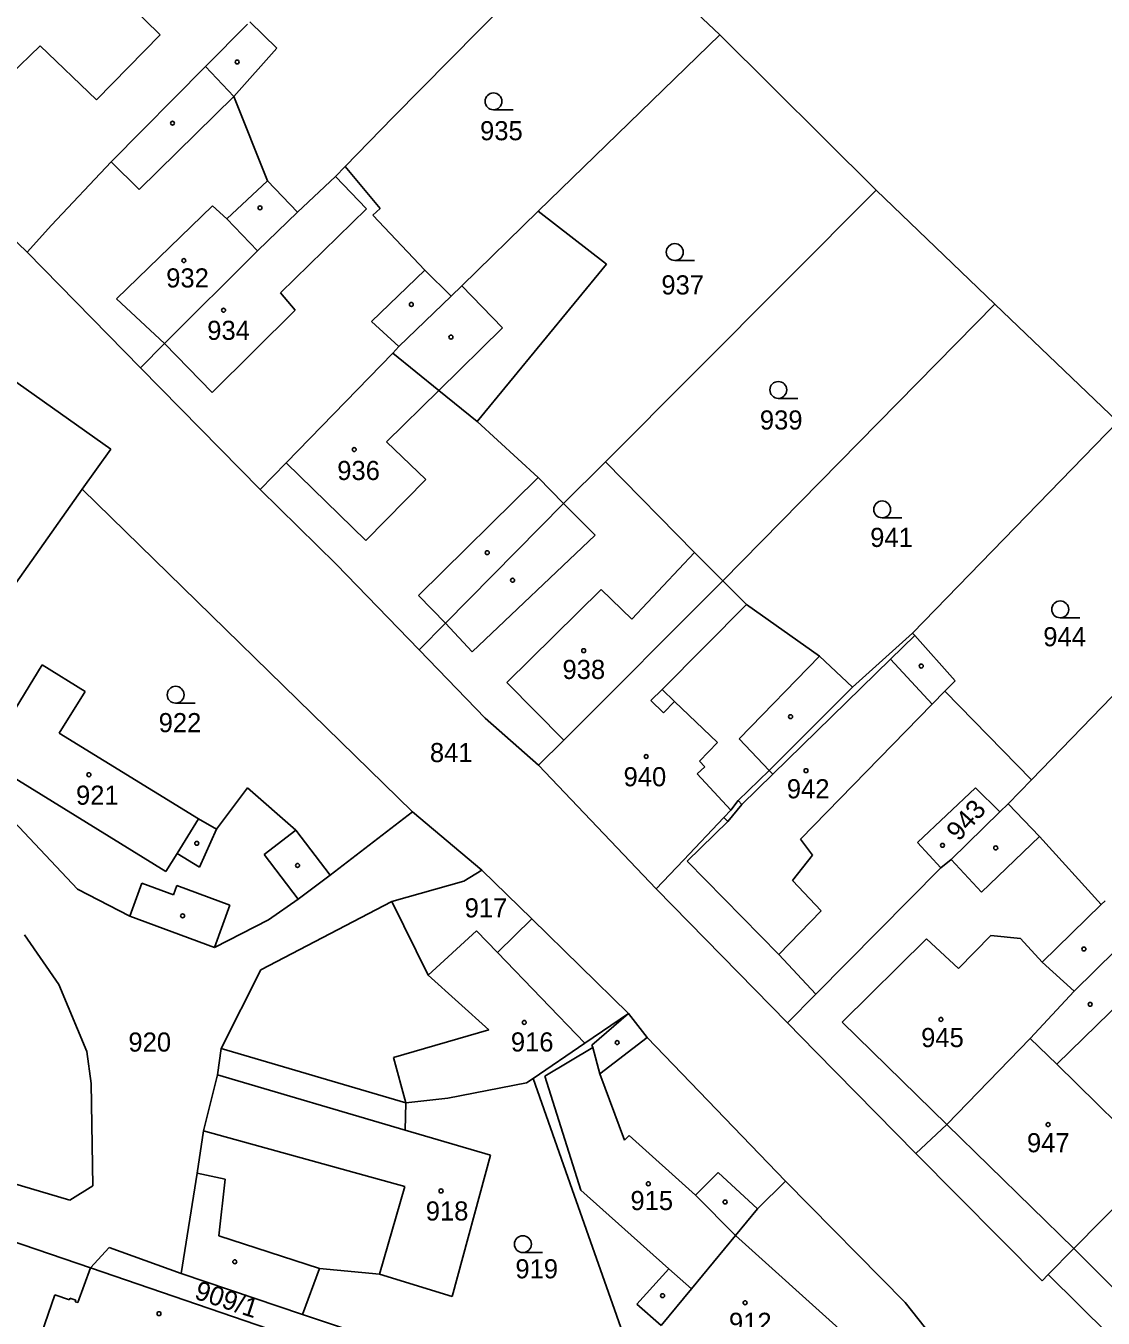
# Model space of a CAD drawing. Extents: x -779596 to -776743, y -1030330 to -1024513.
# Drawn here: x -777631 to -777535.2, y -1025565.5 to -1025450.6 of the extents above; entities that cross this region are included whole.
import ezdxf

# ---------------------------------------------------------------- set-up
doc = ezdxf.new("R2010")
doc.units = 0
for name, color, linetype in [('hranice parcel', 7, 'Continuous'), ('hranice vnitřní', 7, 'Continuous'), ('kultura', 7, 'Continuous'), ('č_ parcel šipka', 7, 'Continuous'), ('č_pacel stav_', 7, 'Continuous'), ('č_parcel poz_', 7, 'Continuous')]:
    doc.layers.add(name, color=color, linetype=linetype)

msp = doc.modelspace()

# ---------------------------------------------------------------- linework, layer by layer
at = {"layer": 'hranice parcel'}
for points in [[(-777629.79, -1025440.88), (-777619.04, -1025451.43)], [(-777598.32, -1025458.73), (-777580.56, -1025440.75)], [(-777580.56, -1025440.75), (-777569.28, -1025451.43)], [(-777611.07, -1025450.25), (-777608.66, -1025452.61)], [(-777615, -1025454.22), (-777611.28, -1025450.46)], [(-777632.41, -1025455), (-777629.71, -1025452.38)], [(-777629.71, -1025452.38), (-777624.69, -1025457.19)], [(-777624.69, -1025457.19), (-777619.04, -1025451.43)], [(-777585.41, -1025467.1), (-777569.28, -1025451.43)], [(-777569.28, -1025451.43), (-777555.38, -1025465.23)], [(-777612.5, -1025456.89), (-777608.66, -1025452.61)], [(-777623.4, -1025462.71), (-777615, -1025454.22)], [(-777612.5, -1025456.89), (-777609.5, -1025464.41)], [(-777602.6, -1025463.12), (-777598.32, -1025458.73)], [(-777628.69, -1025468.34), (-777623.4, -1025462.71)], [(-777606.82, -1025467.18), (-777603.46, -1025464)], [(-777603.46, -1025464), (-777602.6, -1025463.12)], [(-777602.6, -1025463.12), (-777599.48, -1025466.85)], [(-777609.5, -1025464.41), (-777606.82, -1025467.18)], [(-777579.44, -1025489.37), (-777555.38, -1025465.23)], [(-777555.38, -1025465.23), (-777544.81, -1025475.35)], [(-777610.37, -1025470.63), (-777606.82, -1025467.18)], [(-777600.12, -1025467.46), (-777599.48, -1025466.85)], [(-777600.12, -1025467.46), (-777595.49, -1025472.33)], [(-777592.22, -1025473.74), (-777585.41, -1025467.1)], [(-777585.41, -1025467.1), (-777579.34, -1025471.82)], [(-777634.25, -1025467.51), (-777630.86, -1025470.74)], [(-777630.86, -1025470.74), (-777628.69, -1025468.34)], [(-777630.86, -1025470.74), (-777620.79, -1025481.01)], [(-777618.65, -1025478.87), (-777610.37, -1025470.63)], [(-777590.85, -1025485.79), (-777579.34, -1025471.82)], [(-777595.49, -1025472.33), (-777593.16, -1025474.64)], [(-777593.16, -1025474.64), (-777592.22, -1025473.74)], [(-777597.8, -1025479.14), (-777593.16, -1025474.64)], [(-777568.99, -1025499.96), (-777544.81, -1025475.35)], [(-777544.81, -1025475.35), (-777533.87, -1025485.82)], [(-777620.79, -1025481.01), (-777618.65, -1025478.87)], [(-777635.46, -1025479.74), (-777623.41, -1025488.25)], [(-777607.83, -1025489.46), (-777598.35, -1025479.71)], [(-777598.35, -1025479.71), (-777597.8, -1025479.14)], [(-777620.79, -1025481.01), (-777610.14, -1025491.85)], [(-777590.85, -1025485.79), (-777585.43, -1025490.78)], [(-777552.15, -1025504.61), (-777533.87, -1025485.82)], [(-777625.98, -1025491.82), (-777623.41, -1025488.25)], [(-777610.14, -1025491.85), (-777607.83, -1025489.46)], [(-777583.16, -1025493.1), (-777579.44, -1025489.37)], [(-777579.44, -1025489.37), (-777571.52, -1025497.43)], [(-777585.43, -1025490.78), (-777583.16, -1025493.1)], [(-777639.77, -1025511.34), (-777625.98, -1025491.82)], [(-777625.98, -1025491.82), (-777596.6, -1025520.49)], [(-777610.14, -1025491.85), (-777603.39, -1025498.47)], [(-777593.67, -1025503.72), (-777583.16, -1025493.1)], [(-777541.56, -1025517.67), (-777521.9, -1025497.36)], [(-777603.39, -1025498.47), (-777596.02, -1025506.09)], [(-777571.52, -1025497.43), (-777568.99, -1025499.96)], [(-777583.13, -1025514.12), (-777568.99, -1025499.96)], [(-777568.99, -1025499.96), (-777566.89, -1025502.08)], [(-777566.89, -1025502.08), (-777560.42, -1025506.65)], [(-777596.02, -1025506.09), (-777593.67, -1025503.72)], [(-777557.48, -1025509.41), (-777552.15, -1025504.61)], [(-777552.15, -1025504.61), (-777551.94, -1025504.83)], [(-777551.94, -1025504.83), (-777548.35, -1025508.85)], [(-777596.02, -1025506.09), (-777590.13, -1025512.17)], [(-777634.7, -1025515.86), (-777629.53, -1025507.44)], [(-777629.53, -1025507.44), (-777625.71, -1025509.79)], [(-777560.42, -1025506.65), (-777557.48, -1025509.41)], [(-777549.25, -1025509.78), (-777548.35, -1025508.85)], [(-777628.01, -1025513.52), (-777625.71, -1025509.79)], [(-777564.88, -1025516.82), (-777557.48, -1025509.41)], [(-777549.25, -1025509.78), (-777541.56, -1025517.67)], [(-777590.13, -1025512.17), (-777585.4, -1025516.35)], [(-777628.01, -1025513.52), (-777615.64, -1025521.12)], [(-777585.4, -1025516.35), (-777583.13, -1025514.12)], [(-777585.4, -1025516.35), (-777574.92, -1025527.34)], [(-777567.65, -1025519.48), (-777564.88, -1025516.82)], [(-777635.86, -1025517.33), (-777626.39, -1025527.37)], [(-777543.62, -1025519.79), (-777541.56, -1025517.67)], [(-777614.03, -1025522.05), (-777611.28, -1025518.38)], [(-777611.28, -1025518.38), (-777606.97, -1025522.13)], [(-777551.68, -1025523.24), (-777546.55, -1025518.36)], [(-777546.55, -1025518.36), (-777544.36, -1025520.49)], [(-777568.92, -1025521.01), (-777568.3, -1025520.35)], [(-777568.3, -1025520.35), (-777567.65, -1025519.48)], [(-777544.36, -1025520.49), (-777543.62, -1025519.79)], [(-777543.62, -1025519.79), (-777540.86, -1025522.69)], [(-777615.64, -1025521.12), (-777614.03, -1025522.05)], [(-777603.93, -1025526.12), (-777596.6, -1025520.49)], [(-777596.6, -1025520.49), (-777590.42, -1025525.69)], [(-777572.5, -1025524.79), (-777568.92, -1025521.01)], [(-777548.69, -1025524.74), (-777544.36, -1025520.49)], [(-777606.97, -1025522.13), (-777603.93, -1025526.12)], [(-777551.68, -1025523.24), (-777549.63, -1025525.48)], [(-777540.86, -1025522.69), (-777535.36, -1025528.75)], [(-777574.92, -1025527.34), (-777572.5, -1025524.79)], [(-777549.63, -1025525.48), (-777548.69, -1025524.74)], [(-777592.04, -1025526.66), (-777590.42, -1025525.69)], [(-777590.42, -1025525.69), (-777585.99, -1025530.01)], [(-777560.74, -1025536.7), (-777549.63, -1025525.48)], [(-777606.76, -1025528.28), (-777603.93, -1025526.12)], [(-777598.43, -1025528.47), (-777592.04, -1025526.66)], [(-777626.39, -1025527.37), (-777621.74, -1025529.79)], [(-777609.4, -1025530.1), (-777606.76, -1025528.28)], [(-777574.92, -1025527.34), (-777563.26, -1025539.25)], [(-777610.07, -1025534.56), (-777598.43, -1025528.47)], [(-777598.43, -1025528.47), (-777595.21, -1025535.03)], [(-777535.36, -1025528.75), (-777535.01, -1025528.41)], [(-777621.74, -1025529.79), (-777614.21, -1025532.56)], [(-777614.21, -1025532.56), (-777609.4, -1025530.1)], [(-777589.04, -1025533.02), (-777585.99, -1025530.01)], [(-777585.99, -1025530.01), (-777577.38, -1025538.42)], [(-777631.1, -1025531.44), (-777628.04, -1025535.86)], [(-777595.21, -1025535.03), (-777590.91, -1025531.07)], [(-777590.91, -1025531.07), (-777589.04, -1025533.02)], [(-777537.75, -1025536.44), (-777532.18, -1025530.97)], [(-777613.6, -1025541.54), (-777610.07, -1025534.56)], [(-777628.04, -1025535.86), (-777625.56, -1025541.81)], [(-777563.26, -1025539.25), (-777560.74, -1025536.7)], [(-777541.69, -1025540.65), (-777537.75, -1025536.44)], [(-777581.28, -1025541.08), (-777577.38, -1025538.42)], [(-777577.38, -1025538.42), (-777575.73, -1025540.57)], [(-777563.26, -1025539.25), (-777560.72, -1025541.84)], [(-777575.73, -1025540.57), (-777563.42, -1025553.35)], [(-777549.1, -1025548.3), (-777541.69, -1025540.65)], [(-777625.56, -1025541.81), (-777625.17, -1025544.67)], [(-777613.94, -1025543.9), (-777613.6, -1025541.54)], [(-777613.6, -1025541.54), (-777597.2, -1025546.38)], [(-777585.87, -1025544.2), (-777581.28, -1025541.08)], [(-777560.72, -1025541.84), (-777551.84, -1025550.89)], [(-777615.17, -1025548.86), (-777613.94, -1025543.9)], [(-777586.45, -1025544.59), (-777585.87, -1025544.2)], [(-777585.87, -1025544.2), (-777582.41, -1025554.07)], [(-777625.17, -1025544.67), (-777625.01, -1025553.76)], [(-777593.45, -1025545.95), (-777586.45, -1025544.59)], [(-777597.26, -1025548.8), (-777597.2, -1025546.38)], [(-777597.2, -1025546.38), (-777593.45, -1025545.95)], [(-777615.76, -1025552.64), (-777615.17, -1025548.86)], [(-777597.26, -1025548.8), (-777589.66, -1025551.03)], [(-777551.84, -1025550.89), (-777549.1, -1025548.3)], [(-777593.07, -1025563.59), (-777589.66, -1025551.03)], [(-777551.84, -1025550.89), (-777540.62, -1025562.2)], [(-777637.3, -1025552), (-777627.08, -1025555.03)], [(-777537.78, -1025559.34), (-777530.33, -1025551.77)], [(-777617.17, -1025561.54), (-777615.76, -1025552.64)], [(-777565.93, -1025555.81), (-777563.42, -1025553.35)], [(-777563.42, -1025553.35), (-777552.8, -1025564.12)], [(-777627.08, -1025555.03), (-777625.01, -1025553.76)], [(-777582.41, -1025554.07), (-777577.17, -1025568.88)], [(-777567.89, -1025558.18), (-777565.93, -1025555.81)], [(-777638.45, -1025556.54), (-777625.22, -1025561.06)], [(-777571.8, -1025562.91), (-777567.89, -1025558.18)], [(-777625.22, -1025561.06), (-777623.56, -1025559.23)], [(-777623.56, -1025559.23), (-777617.17, -1025561.54)], [(-777540.06, -1025561.64), (-777537.78, -1025559.34)], [(-777625.22, -1025561.06), (-777626.36, -1025564.14)], [(-777625.22, -1025561.06), (-777609.4, -1025566.46)], [(-777617.17, -1025561.54), (-777606.38, -1025565.2)], [(-777606.38, -1025565.2), (-777604.87, -1025561.1)], [(-777604.87, -1025561.1), (-777599.54, -1025561.62)], [(-777599.54, -1025561.62), (-777593.07, -1025563.59)], [(-777540.62, -1025562.2), (-777540.06, -1025561.64)], [(-777540.06, -1025561.64), (-777529.23, -1025572.36)], [(-777628.41, -1025563.46), (-777630.48, -1025569.46)], [(-777627.11, -1025563.9), (-777628.41, -1025563.46)], [(-777627.06, -1025563.74), (-777627.11, -1025563.9)], [(-777626.53, -1025563.91), (-777627.06, -1025563.74)], [(-777626.59, -1025564.07), (-777626.53, -1025563.91)], [(-777574.49, -1025566.17), (-777571.8, -1025562.91)], [(-777626.36, -1025564.14), (-777626.59, -1025564.07)], [(-777552.8, -1025564.12), (-777550.41, -1025567.13)], [(-777606.38, -1025565.2), (-777600.96, -1025566.99)]]:
    msp.add_lwpolyline(points, dxfattribs=at)
at = {"layer": 'hranice vnitřní'}
for points in [[(-777615, -1025454.22), (-777612.5, -1025456.89)], [(-777620.89, -1025465.18), (-777612.5, -1025456.89)], [(-777623.4, -1025462.71), (-777620.89, -1025465.18)], [(-777603.46, -1025464), (-777600.68, -1025466.88)], [(-777613.11, -1025467.78), (-777609.5, -1025464.41)], [(-777622.91, -1025474.9), (-777614.37, -1025466.61)], [(-777614.37, -1025466.61), (-777613.11, -1025467.78)], [(-777608.35, -1025474.35), (-777600.68, -1025466.88)], [(-777613.11, -1025467.78), (-777610.37, -1025470.63)], [(-777600.25, -1025476.9), (-777595.49, -1025472.33)], [(-777608.35, -1025474.35), (-777607.03, -1025475.91)], [(-777592.22, -1025473.74), (-777588.59, -1025477.48)], [(-777622.91, -1025474.9), (-777618.65, -1025478.87)], [(-777614.4, -1025483.23), (-777607.03, -1025475.91)], [(-777600.25, -1025476.9), (-777597.8, -1025479.14)], [(-777594.25, -1025483.03), (-777588.59, -1025477.48)], [(-777618.65, -1025478.87), (-777614.4, -1025483.23)], [(-777598.35, -1025479.71), (-777594.25, -1025483.03)], [(-777598.91, -1025487.6), (-777594.25, -1025483.03)], [(-777594.25, -1025483.03), (-777590.85, -1025485.79)], [(-777598.91, -1025487.6), (-777595.42, -1025490.94)], [(-777607.83, -1025489.46), (-777600.75, -1025496.39)], [(-777600.75, -1025496.39), (-777595.42, -1025490.94)], [(-777596.07, -1025501.28), (-777585.43, -1025490.78)], [(-777583.16, -1025493.1), (-777580.37, -1025495.91)], [(-777591.29, -1025506.28), (-777580.37, -1025495.91)], [(-777577.11, -1025503.37), (-777571.52, -1025497.43)], [(-777588.22, -1025509.01), (-777579.83, -1025500.72)], [(-777579.83, -1025500.72), (-777577.11, -1025503.37)], [(-777596.07, -1025501.28), (-777593.67, -1025503.72)], [(-777574.41, -1025509.61), (-777566.89, -1025502.08)], [(-777593.67, -1025503.72), (-777591.29, -1025506.28)], [(-777554.08, -1025506.92), (-777551.94, -1025504.83)], [(-777567.54, -1025514.01), (-777560.42, -1025506.65)], [(-777564.56, -1025517.16), (-777554.08, -1025506.92)], [(-777554.08, -1025506.92), (-777550.38, -1025510.93)], [(-777588.22, -1025509.01), (-777583.13, -1025514.12)], [(-777575.41, -1025510.61), (-777574.41, -1025509.61)], [(-777574.41, -1025509.61), (-777573.29, -1025510.68)], [(-777550.38, -1025510.93), (-777549.25, -1025509.78)], [(-777575.41, -1025510.61), (-777574.28, -1025511.71)], [(-777574.28, -1025511.71), (-777573.29, -1025510.68)], [(-777573.29, -1025510.68), (-777569.48, -1025514.35)], [(-777562.11, -1025522.92), (-777550.38, -1025510.93)], [(-777571.07, -1025516), (-777569.48, -1025514.35)], [(-777567.54, -1025514.01), (-777564.88, -1025516.82)], [(-777634.7, -1025515.86), (-777618.52, -1025525.8)], [(-777571.28, -1025517.12), (-777570.61, -1025516.5)], [(-777571.07, -1025516), (-777570.61, -1025516.5)], [(-777564.88, -1025516.82), (-777564.56, -1025517.16)], [(-777571.28, -1025517.12), (-777568.3, -1025520.35)], [(-777567.3, -1025519.84), (-777564.56, -1025517.16)], [(-777568.55, -1025521.35), (-777567.3, -1025519.84)], [(-777567.65, -1025519.48), (-777567.3, -1025519.84)], [(-777617.53, -1025524.2), (-777615.64, -1025521.12)], [(-777572.18, -1025524.89), (-777568.55, -1025521.35)], [(-777568.92, -1025521.01), (-777568.55, -1025521.35)], [(-777615.55, -1025525.42), (-777614.03, -1025522.05)], [(-777609.8, -1025524.29), (-777606.97, -1025522.13)], [(-777562.11, -1025522.92), (-777561.04, -1025524.34)], [(-777546.01, -1025527.64), (-777540.86, -1025522.69)], [(-777618.52, -1025525.8), (-777617.53, -1025524.2)], [(-777617.53, -1025524.2), (-777615.55, -1025525.42)], [(-777609.8, -1025524.29), (-777606.76, -1025528.28)], [(-777572.18, -1025524.89), (-777564.01, -1025533.2)], [(-777562.82, -1025526.6), (-777561.04, -1025524.34)], [(-777548.69, -1025524.74), (-777546.01, -1025527.64)], [(-777621.74, -1025529.79), (-777620.66, -1025526.84)], [(-777620.66, -1025526.84), (-777617.85, -1025527.87)], [(-777617.85, -1025527.87), (-777617.56, -1025527.06)], [(-777617.56, -1025527.06), (-777612.83, -1025528.79)], [(-777562.82, -1025526.6), (-777560.25, -1025529.29)], [(-777614.21, -1025532.56), (-777612.83, -1025528.79)], [(-777564.01, -1025533.2), (-777560.25, -1025529.29)], [(-777540.61, -1025533.88), (-777535.36, -1025528.75)], [(-777558.4, -1025539.21), (-777550.9, -1025531.8)], [(-777550.9, -1025531.8), (-777548.05, -1025534.44)], [(-777548.05, -1025534.44), (-777545.17, -1025531.51)], [(-777545.17, -1025531.51), (-777542.54, -1025531.77)], [(-777542.54, -1025531.77), (-777540.61, -1025533.88)], [(-777589.04, -1025533.02), (-777581.28, -1025541.08)], [(-777564.01, -1025533.2), (-777560.74, -1025536.7)], [(-777540.61, -1025533.88), (-777537.75, -1025536.44)], [(-777595.21, -1025535.03), (-777589.8, -1025539.88)], [(-777539.31, -1025542.95), (-777532.22, -1025536.02)], [(-777580.64, -1025541.26), (-777577.38, -1025538.42)], [(-777598.29, -1025542.33), (-777589.8, -1025539.88)], [(-777558.4, -1025539.21), (-777549.1, -1025548.3)], [(-777579.94, -1025543.8), (-777575.73, -1025540.57)], [(-777541.69, -1025540.65), (-777539.31, -1025542.95)], [(-777584.83, -1025543.99), (-777580.57, -1025541.47)], [(-777580.64, -1025541.26), (-777580.57, -1025541.47)], [(-777580.57, -1025541.47), (-777579.94, -1025543.8)], [(-777598.29, -1025542.33), (-777597.2, -1025546.38)], [(-777539.31, -1025542.95), (-777530.33, -1025551.77)], [(-777613.94, -1025543.9), (-777597.26, -1025548.8)], [(-777584.83, -1025543.99), (-777581.62, -1025554.14)], [(-777579.94, -1025543.8), (-777577.74, -1025549.69)], [(-777615.17, -1025548.86), (-777597.28, -1025553.81)], [(-777549.1, -1025548.3), (-777537.78, -1025559.34)], [(-777577.74, -1025549.69), (-777577.33, -1025549.29)], [(-777577.33, -1025549.29), (-777571.43, -1025554.57)], [(-777615.76, -1025552.64), (-777613.27, -1025553.15)], [(-777613.83, -1025558.21), (-777613.27, -1025553.15)], [(-777571.43, -1025554.57), (-777569.41, -1025552.56)], [(-777569.41, -1025552.56), (-777565.93, -1025555.81)], [(-777599.54, -1025561.62), (-777597.28, -1025553.81)], [(-777581.62, -1025554.14), (-777573.8, -1025561.13)], [(-777571.43, -1025554.57), (-777567.89, -1025558.18)], [(-777613.83, -1025558.21), (-777604.87, -1025561.1)], [(-777567.89, -1025558.18), (-777558.36, -1025566.74)], [(-777537.78, -1025559.34), (-777527, -1025570.13)], [(-777576.66, -1025564.29), (-777573.8, -1025561.13)], [(-777573.8, -1025561.13), (-777571.8, -1025562.91)], [(-777576.66, -1025564.29), (-777574.49, -1025566.17)]]:
    msp.add_lwpolyline(points, dxfattribs=at)
at = {"layer": 'kultura'}
for points in [[(-777589.4, -1025458.08), (-777587.65, -1025458.08)], [(-777573.28, -1025471.48), (-777571.53, -1025471.48)], [(-777564.07, -1025483.74), (-777562.32, -1025483.74)], [(-777554.84, -1025494.36), (-777553.09, -1025494.36)], [(-777539, -1025503.25), (-777537.25, -1025503.25)], [(-777617.66, -1025510.84), (-777615.91, -1025510.84)], [(-777586.78, -1025559.69), (-777585.03, -1025559.69)]]:
    msp.add_lwpolyline(points, dxfattribs=at)
for centre, radius in [((-777612.19, -1025453.83), 0.175), ((-777589.4, -1025457.33), 0.75), ((-777617.94, -1025459.27), 0.175), ((-777610.16, -1025466.8), 0.175), ((-777573.28, -1025470.73), 0.75), ((-777616.93, -1025471.49), 0.175), ((-777596.7, -1025475.39), 0.175), ((-777613.4, -1025475.9), 0.175), ((-777593.18, -1025478.29), 0.175), ((-777564.07, -1025482.99), 0.75), ((-777601.78, -1025488.29), 0.175), ((-777554.84, -1025493.61), 0.75), ((-777589.95, -1025497.46), 0.175), ((-777587.7, -1025499.91), 0.175), ((-777539, -1025502.5), 0.75), ((-777581.38, -1025506.17), 0.175), ((-777551.36, -1025507.54), 0.175), ((-777617.66, -1025510.09), 0.75), ((-777562.98, -1025512.04), 0.175), ((-777575.82, -1025515.58), 0.175), ((-777561.61, -1025516.84), 0.175), ((-777625.37, -1025517.2), 0.175), ((-777615.78, -1025523.3), 0.175), ((-777549.47, -1025523.48), 0.175), ((-777544.74, -1025523.71), 0.175), ((-777606.82, -1025525.27), 0.175), ((-777617.04, -1025529.75), 0.175), ((-777536.9, -1025532.7), 0.175), ((-777536.34, -1025537.62), 0.175), ((-777586.66, -1025539.23), 0.175), ((-777549.61, -1025538.96), 0.175), ((-777578.4, -1025541.02), 0.175), ((-777540.08, -1025548.31), 0.175), ((-777575.63, -1025553.57), 0.175), ((-777594.06, -1025554.21), 0.175), ((-777568.8, -1025555.19), 0.175), ((-777586.78, -1025558.94), 0.75), ((-777612.4, -1025560.51), 0.175), ((-777574.36, -1025563.52), 0.175), ((-777567.02, -1025564.15), 0.175), ((-777619.14, -1025565.12), 0.175)]:
    msp.add_circle(centre, radius, dxfattribs=at)

# ---------------------------------------------------------------- texts
at = {"layer": 'č_ parcel šipka'}
msp.add_text('841', height=1.7, dxfattribs=at).set_placement((-777595.05, -1025516.08))
at = {"layer": 'č_pacel stav_'}
for s, p in [('932', (-777618.5, -1025473.88)), ('934', (-777614.85, -1025478.54)), ('936', (-777603.29, -1025491)), ('938', (-777583.26, -1025508.69)), ('940', (-777577.83, -1025518.23)), ('942', (-777563.31, -1025519.3)), ('921', (-777626.52, -1025519.87)), ('945', (-777551.37, -1025541.42)), ('916', (-777587.85, -1025541.81)), ('947', (-777541.96, -1025550.77)), ('915', (-777577.22, -1025555.91)), ('918', (-777595.42, -1025556.84)), ('912', (-777568.46, -1025566.74))]:
    msp.add_text(s, height=1.7, dxfattribs=at).set_placement(p)
msp.add_text('943', height=1.7, rotation=48.20038, dxfattribs=at).set_placement((-777548.025, -1025523.198))
at = {"layer": 'č_parcel poz_'}
for s, p in [('935', (-777590.59, -1025460.79)), ('937', (-777574.47, -1025474.5)), ('939', (-777565.71, -1025486.51)), ('941', (-777555.9, -1025496.95)), ('944', (-777540.51, -1025505.78)), ('922', (-777619.17, -1025513.42)), ('917', (-777591.96, -1025529.89)), ('920', (-777621.86, -1025541.82)), ('919', (-777587.45, -1025561.98))]:
    msp.add_text(s, height=1.7, dxfattribs=at).set_placement(p)
msp.add_text('909/1', height=1.7, rotation=341.80272, dxfattribs=at).set_placement((-777616.078, -1025563.763))

doc.saveas('drawing.dxf')
